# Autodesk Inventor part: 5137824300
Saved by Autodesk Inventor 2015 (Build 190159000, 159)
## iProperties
Created: 2020-07
Part Number: 5137824300
Checked By: TraceParts S.A.
Material: Generic
Catalog Web Link: www.traceparts.com
Document SubType Name: Modeling
Designer: TraceParts
Density: 1 g/cm^3
Appearance: Default
Company: TraceParts S.A.
Author: TraceParts
REFERENCE: 5137824300
DESIGN: CVAT/4-12000/560 N D PTC 2,2KW (230/400V) 50HZ - 5137824300
SUPPLIER: Soler & Palau
TraceParts.PartNumber: 10-14122018-105188
TraceParts.PartTitle: CVAT-N
TraceParts.InstanceId: 10-14122018-105188CUC25C8IN8UOFSDEJYQD1QGCN
TraceParts.PartStatus: Published
TraceParts.PartVersion: 1.0.4
TRACEPARTS: TRACEPARTS
TraceParts.PartLanguage: en
TraceParts.ClassPath: SOLER_PALAU:10-14122018-105188
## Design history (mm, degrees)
feature "5137824300"
body "Solid1"
